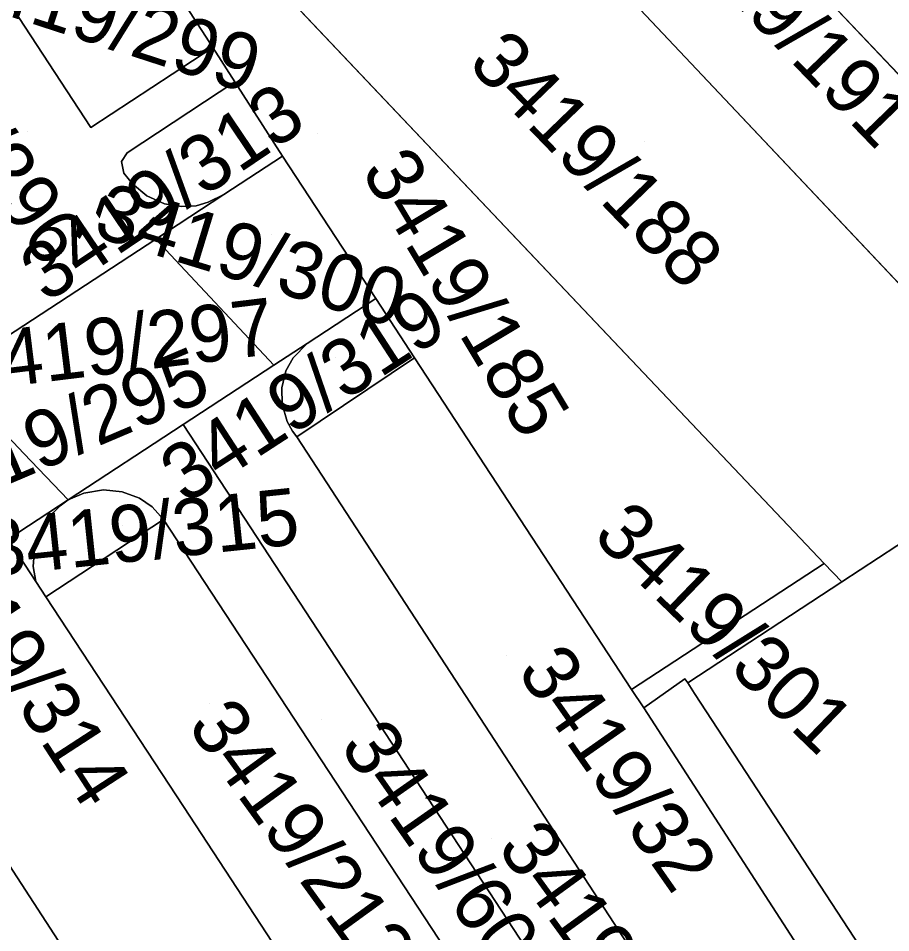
# Model space of a CAD drawing. Extents: x -262715 to -259381, y -1237238 to -1231182.
# Drawn here: x -261973.76 to -261943.03, y -1235771.55 to -1235739.35 of the extents above; entities that cross this region are included whole.
import ezdxf

# ---------------------------------------------------------------- set-up
doc = ezdxf.new("R2010")
doc.units = 0
for name, color, linetype in [('body_kn', 7, 'Continuous'), ('kladpar_druhypozemkov', 7, 'Continuous'), ('kladpar_hranice', 7, 'Continuous'), ('kladpar_parcelnecisla', 7, 'Continuous'), ('kladpar_plochy', 7, 'Continuous'), ('kladpar_sipky', 7, 'Continuous')]:
    doc.layers.add(name, color=color, linetype=linetype)

msp = doc.modelspace()

# ---------------------------------------------------------------- linework, layer by layer
at = {"layer": 'body_kn'}
for p, q in [((-261966.91, -1235740.38), (-261966.91, -1235740.38)), ((-261966.91, -1235740.38), (-261966.91, -1235740.38)), ((-261966.13, -1235741.59), (-261966.13, -1235741.59)), ((-261971.21, -1235743.19), (-261971.21, -1235743.19)), ((-261969.92, -1235744.09), (-261969.92, -1235744.09)), ((-261964.45, -1235744.2), (-261964.45, -1235744.2)), ((-261964.45, -1235744.2), (-261964.45, -1235744.2)), ((-261970.12, -1235744.39), (-261970.12, -1235744.39)), ((-261970.04, -1235744.81), (-261970.04, -1235744.81)), ((-261969.74, -1235745.18), (-261969.74, -1235745.18)), ((-261966.52, -1235745.55), (-261966.52, -1235745.55)), ((-261969.23, -1235745.6), (-261969.23, -1235745.6)), ((-261967.07, -1235745.83), (-261967.07, -1235745.83)), ((-261968.61, -1235745.89), (-261968.61, -1235745.89)), ((-261968.01, -1235745.98), (-261968.01, -1235745.98)), ((-261967.5, -1235745.96), (-261967.5, -1235745.96)), ((-261968.92, -1235747.13), (-261968.92, -1235747.13)), ((-261968.92, -1235747.13), (-261968.92, -1235747.13)), ((-261961.17, -1235749.22), (-261961.17, -1235749.22)), ((-261963.58, -1235750.8), (-261963.58, -1235750.8)), ((-261964.08, -1235751.31), (-261964.08, -1235751.31)), ((-261959.8, -1235751.31), (-261959.8, -1235751.31)), ((-261959.8, -1235751.31), (-261959.8, -1235751.31)), ((-261964.76, -1235751.57), (-261964.76, -1235751.57)), ((-261964.76, -1235751.57), (-261964.76, -1235751.57)), ((-261964.33, -1235751.77), (-261964.33, -1235751.77)), ((-261964.48, -1235752.37), (-261964.48, -1235752.37)), ((-261964.47, -1235752.94), (-261964.47, -1235752.94)), ((-261964.29, -1235753.55), (-261964.29, -1235753.55)), ((-261967.95, -1235753.66), (-261967.95, -1235753.66)), ((-261967.95, -1235753.66), (-261967.95, -1235753.66)), ((-261964.1, -1235753.89), (-261964.1, -1235753.89)), ((-261963.95, -1235754.09), (-261963.95, -1235754.09)), ((-261963.95, -1235754.09), (-261963.95, -1235754.09)), ((-261973.56, -1235754.68), (-261973.56, -1235754.68)), ((-261971.45, -1235756.07), (-261971.45, -1235756.07)), ((-261970.76, -1235755.96), (-261970.76, -1235755.96)), ((-261970.1, -1235756.03), (-261970.1, -1235756.03)), ((-261972, -1235756.31), (-261972, -1235756.31)), ((-261972, -1235756.31), (-261972, -1235756.31)), ((-261969.49, -1235756.25), (-261969.49, -1235756.25)), ((-261972.29, -1235756.52), (-261972.29, -1235756.52)), ((-261969.05, -1235756.56), (-261969.05, -1235756.56)), ((-261972.72, -1235756.94), (-261972.72, -1235756.94)), ((-261968.64, -1235757), (-261968.64, -1235757)), ((-261968.64, -1235757), (-261968.64, -1235757)), ((-261973.06, -1235757.55), (-261973.06, -1235757.55)), ((-261973.19, -1235758.06), (-261973.19, -1235758.06)), ((-261973.24, -1235758.66), (-261973.24, -1235758.66)), ((-261945.37, -1235758.55), (-261945.37, -1235758.55)), ((-261945.37, -1235758.55), (-261945.37, -1235758.55)), ((-261973.14, -1235759.18), (-261973.14, -1235759.18)), ((-261944.75, -1235759.2), (-261944.75, -1235759.2)), ((-261944.75, -1235759.2), (-261944.75, -1235759.2)), ((-261972.79, -1235759.72), (-261972.79, -1235759.72)), ((-261972.79, -1235759.72), (-261972.79, -1235759.72)), ((-261950.28, -1235762.61), (-261950.28, -1235762.61)), ((-261950.18, -1235762.76), (-261950.18, -1235762.76)), ((-261950.18, -1235762.76), (-261950.18, -1235762.76)), ((-261952.16, -1235762.99), (-261952.16, -1235762.99)), ((-261949.94, -1235763.13), (-261949.94, -1235763.13)), ((-261951.72, -1235763.63), (-261951.72, -1235763.63)), ((-261951.72, -1235763.63), (-261951.72, -1235763.63)), ((-261967.94, -1235767.11), (-261967.94, -1235767.11)), ((-261973.07, -1235770.72), (-261973.07, -1235770.72))]:
    msp.add_line(p, q, dxfattribs=at)
at = {"layer": 'kladpar_druhypozemkov'}
for p, q in [((-261973.42, -1235743.34), (-261973.42, -1235743.34)), ((-261963.23, -1235743.41), (-261963.23, -1235743.41)), ((-261967.62, -1235743.88), (-261967.62, -1235743.88)), ((-261951.7, -1235743.7), (-261951.7, -1235743.7)), ((-261964.83, -1235746.95), (-261964.83, -1235746.95)), ((-261970.19, -1235750.28), (-261970.19, -1235750.28)), ((-261962.57, -1235751.28), (-261962.57, -1235751.28)), ((-261970.09, -1235757.23), (-261970.09, -1235757.23)), ((-261973.49, -1235757.71), (-261973.49, -1235757.71)), ((-261947.28, -1235760.58), (-261947.28, -1235760.58)), ((-261956.55, -1235761.78), (-261956.55, -1235761.78)), ((-261967.01, -1235763.47), (-261967.01, -1235763.47)), ((-261963.07, -1235764.03), (-261963.07, -1235764.03)), ((-261957.08, -1235768.25), (-261957.08, -1235768.25))]:
    msp.add_line(p, q, dxfattribs=at)
at = {"layer": 'kladpar_hranice'}
for p, q in [((-261933.69, -1235750.9), (-261955.68, -1235727.67)), ((-261955.68, -1235727.67), (-261933.69, -1235750.9)), ((-261938, -1235753.72), (-261959.95, -1235730.45)), ((-261967.39, -1235735.31), (-261945.37, -1235758.55)), ((-261964.76, -1235751.57), (-261968.92, -1235747.13)), ((-261968.92, -1235747.13), (-261964.76, -1235751.57)), ((-261972, -1235756.31), (-261974.12, -1235757.69)), ((-261945.37, -1235758.55), (-261944.75, -1235759.2)), ((-261944.75, -1235759.2), (-261950.18, -1235762.76))]:
    msp.add_line(p, q, dxfattribs=at)
for points in [[(-262003.07, -1235715.88), (-261995.02, -1235727.16), (-261984.24, -1235742.27), (-261982.65, -1235744.7), (-261981.81, -1235745.97), (-261978.73, -1235750.67), (-261978.42, -1235751.14), (-261977.41, -1235752.68), (-261974.12, -1235757.69), (-261973.14, -1235759.18), (-261972.79, -1235759.72), (-261967.94, -1235767.11), (-261964.38, -1235772.54), (-261961.64, -1235776.72), (-261949.4, -1235795.38), (-261942.77, -1235806.52), (-261928.71, -1235830.14), (-261924.58, -1235837.08), (-261915.18, -1235853.36)], [(-261931.33, -1235851.2), (-261935.73, -1235843.8), (-261960.13, -1235804.5), (-261979.55, -1235774.83), (-261996.35, -1235748.74), (-262013.51, -1235721.8), (-262007.21, -1235718.92), (-262002.02, -1235726.66), (-261988.64, -1235746.76), (-261973.07, -1235770.72), (-261954.28, -1235799.67), (-261929.13, -1235840.69), (-261916.72, -1235862.21), (-261911.45, -1235872.23)], [(-261911.45, -1235872.23), (-261916.72, -1235862.21), (-261929.13, -1235840.69), (-261954.28, -1235799.67), (-261973.07, -1235770.72), (-261988.64, -1235746.76), (-262002.02, -1235726.66), (-262007.21, -1235718.92)], [(-261959.95, -1235730.45), (-261938, -1235753.72), (-261937.38, -1235754.37)], [(-261945.37, -1235758.55), (-261952.16, -1235762.99), (-261959.8, -1235751.31), (-261961.17, -1235749.22), (-261964.45, -1235744.2), (-261966.13, -1235741.59), (-261966.91, -1235740.38), (-261969.84, -1235735.84), (-261970.23, -1235735.23), (-261970.52, -1235734.74), (-261970.16, -1235734.55), (-261969.03, -1235736.38), (-261967.39, -1235735.31)], [(-261975.6, -1235738.81), (-261970.23, -1235735.23), (-261969.84, -1235735.84), (-261974.16, -1235738.67), (-261971.21, -1235743.19), (-261966.91, -1235740.38), (-261966.13, -1235741.59), (-261969.92, -1235744.09), (-261970.12, -1235744.39), (-261970.04, -1235744.81), (-261969.74, -1235745.18), (-261969.23, -1235745.6), (-261968.61, -1235745.89), (-261968.01, -1235745.98), (-261967.5, -1235745.96), (-261967.07, -1235745.83), (-261966.52, -1235745.55), (-261968.92, -1235747.13), (-261975.44, -1235751.39)], [(-261944.75, -1235759.2), (-261945.37, -1235758.55), (-261967.39, -1235735.31)], [(-261966.91, -1235740.38), (-261971.21, -1235743.19), (-261974.16, -1235738.67), (-261969.84, -1235735.84), (-261966.91, -1235740.38)], [(-261941.49, -1235776.06), (-261949.94, -1235763.13), (-261950.18, -1235762.76), (-261944.75, -1235759.2), (-261940.87, -1235756.66), (-261942.45, -1235754.27), (-261940.52, -1235752.99), (-261938.94, -1235755.39), (-261937.38, -1235754.37), (-261933.08, -1235751.55), (-261929.13, -1235748.97), (-261922.69, -1235744.74), (-261919.47, -1235742.63), (-261916.3, -1235740.55), (-261916, -1235741.01), (-261910.41, -1235749.59), (-261905.01, -1235757.89), (-261902.93, -1235761.09)], [(-261964.45, -1235744.2), (-261966.52, -1235745.55), (-261967.07, -1235745.83), (-261967.5, -1235745.96), (-261968.01, -1235745.98), (-261968.61, -1235745.89), (-261969.23, -1235745.6), (-261969.74, -1235745.18), (-261970.04, -1235744.81), (-261970.12, -1235744.39), (-261969.92, -1235744.09), (-261966.13, -1235741.59), (-261964.45, -1235744.2)], [(-261968.92, -1235747.13), (-261966.52, -1235745.55), (-261964.45, -1235744.2), (-261961.17, -1235749.22), (-261963.58, -1235750.8), (-261964.76, -1235751.57)], [(-261976.2, -1235751.89), (-261975.44, -1235751.39), (-261968.92, -1235747.13)], [(-261959.8, -1235751.31), (-261963.95, -1235754.09), (-261964.1, -1235753.89), (-261964.29, -1235753.55), (-261964.47, -1235752.94), (-261964.48, -1235752.37), (-261964.33, -1235751.77), (-261964.08, -1235751.31), (-261963.58, -1235750.8), (-261961.17, -1235749.22), (-261959.8, -1235751.31)], [(-261967.95, -1235753.66), (-261964.76, -1235751.57), (-261963.58, -1235750.8), (-261964.08, -1235751.31), (-261964.33, -1235751.77), (-261964.48, -1235752.37), (-261964.47, -1235752.94), (-261964.29, -1235753.55), (-261964.1, -1235753.89), (-261963.95, -1235754.09), (-261946.67, -1235780.57)], [(-261963.95, -1235754.09), (-261959.8, -1235751.31), (-261952.16, -1235762.99), (-261951.72, -1235763.63), (-261942.53, -1235777.85), (-261946.67, -1235780.57), (-261963.95, -1235754.09)], [(-261964.76, -1235751.57), (-261967.95, -1235753.66), (-261972, -1235756.31)], [(-261972, -1235756.31), (-261973.56, -1235754.68), (-261976.2, -1235751.89)], [(-261976.2, -1235751.89), (-261973.56, -1235754.68), (-261972, -1235756.31)], [(-261937.38, -1235754.37), (-261938.94, -1235755.39), (-261940.52, -1235752.99), (-261942.45, -1235754.27), (-261940.87, -1235756.66), (-261944.75, -1235759.2)], [(-261972, -1235756.31), (-261967.95, -1235753.66), (-261945.97, -1235787.22), (-261946.38, -1235792.77)], [(-261946.38, -1235792.77), (-261945.97, -1235787.22), (-261967.95, -1235753.66)], [(-261968.64, -1235757), (-261972.79, -1235759.72), (-261973.14, -1235759.18), (-261973.24, -1235758.66), (-261973.19, -1235758.06), (-261973.06, -1235757.55), (-261972.72, -1235756.94), (-261972.29, -1235756.52), (-261972, -1235756.31), (-261971.45, -1235756.07), (-261970.76, -1235755.96), (-261970.1, -1235756.03), (-261969.49, -1235756.25), (-261969.05, -1235756.56), (-261968.64, -1235757)], [(-261951, -1235787.91), (-261950.81, -1235787.69), (-261950.56, -1235787.38), (-261950.29, -1235786.93), (-261950.15, -1235786.47), (-261950.12, -1235786.02), (-261950.17, -1235785.56), (-261950.35, -1235785.02), (-261950.58, -1235784.59), (-261957.27, -1235774.34), (-261968.64, -1235757), (-261969.05, -1235756.56), (-261969.49, -1235756.25), (-261970.1, -1235756.03), (-261970.76, -1235755.96), (-261971.45, -1235756.07), (-261972, -1235756.31)], [(-261972, -1235756.31), (-261972.29, -1235756.52), (-261972.72, -1235756.94), (-261973.06, -1235757.55), (-261973.19, -1235758.06), (-261973.24, -1235758.66), (-261973.14, -1235759.18), (-261974.12, -1235757.69), (-261972, -1235756.31)], [(-261972.79, -1235759.72), (-261968.64, -1235757), (-261957.27, -1235774.34), (-261959.54, -1235775.81), (-261961.35, -1235777.03)], [(-261950.18, -1235762.76), (-261950.28, -1235762.61), (-261951.72, -1235763.63), (-261952.16, -1235762.99), (-261945.37, -1235758.55)], [(-261961.64, -1235776.72), (-261964.38, -1235772.54), (-261967.94, -1235767.11), (-261972.79, -1235759.72)], [(-261951.72, -1235763.63), (-261950.28, -1235762.61), (-261950.18, -1235762.76), (-261949.94, -1235763.13), (-261941.49, -1235776.06), (-261936.77, -1235783.27), (-261941.58, -1235786.56), (-261941.84, -1235786.72), (-261942.15, -1235786.76), (-261942.48, -1235786.71), (-261942.8, -1235786.46), (-261946.67, -1235780.57), (-261942.53, -1235777.85), (-261951.72, -1235763.63)]]:
    msp.add_lwpolyline(points, dxfattribs=at)
at = {"layer": 'kladpar_plochy'}
for points in [[(-261916.72, -1235862.21), (-261929.13, -1235840.69), (-261954.28, -1235799.67), (-261973.07, -1235770.72), (-261988.64, -1235746.76), (-262002.02, -1235726.66), (-262007.21, -1235718.92), (-262019.79, -1235696.69)], [(-262003.07, -1235715.88), (-261995.02, -1235727.16), (-261984.24, -1235742.27), (-261982.65, -1235744.7), (-261981.81, -1235745.97), (-261978.73, -1235750.67), (-261978.42, -1235751.14), (-261977.41, -1235752.68), (-261974.12, -1235757.69), (-261973.14, -1235759.18), (-261972.79, -1235759.72), (-261967.94, -1235767.11), (-261964.38, -1235772.54), (-261961.64, -1235776.72), (-261949.4, -1235795.38), (-261942.77, -1235806.52), (-261928.71, -1235830.14), (-261924.58, -1235837.08), (-261915.18, -1235853.36)], [(-261975.6, -1235738.81), (-261970.23, -1235735.23), (-261969.84, -1235735.84), (-261974.16, -1235738.67), (-261971.21, -1235743.19), (-261966.91, -1235740.38), (-261966.13, -1235741.59), (-261969.92, -1235744.09), (-261970.12, -1235744.39), (-261970.04, -1235744.81), (-261969.74, -1235745.18), (-261969.23, -1235745.6), (-261968.61, -1235745.89), (-261968.01, -1235745.98), (-261967.5, -1235745.96), (-261967.07, -1235745.83), (-261966.52, -1235745.55), (-261968.92, -1235747.13), (-261975.44, -1235751.39)], [(-261941.49, -1235776.06), (-261949.94, -1235763.13), (-261950.18, -1235762.76), (-261944.75, -1235759.2), (-261940.87, -1235756.66), (-261942.45, -1235754.27), (-261940.52, -1235752.99), (-261938.94, -1235755.39), (-261937.38, -1235754.37), (-261933.08, -1235751.55), (-261929.13, -1235748.97), (-261922.69, -1235744.74), (-261919.47, -1235742.63), (-261916.3, -1235740.55), (-261916, -1235741.01), (-261910.41, -1235749.59), (-261905.01, -1235757.89), (-261902.93, -1235761.09), (-261905.58, -1235762.82), (-261912.05, -1235767.06), (-261915.99, -1235769.64), (-261920.27, -1235772.45)], [(-261945.97, -1235787.22), (-261967.95, -1235753.66), (-261964.76, -1235751.57), (-261963.58, -1235750.8), (-261964.08, -1235751.31), (-261964.33, -1235751.77), (-261964.48, -1235752.37), (-261964.47, -1235752.94), (-261964.29, -1235753.55), (-261964.1, -1235753.89), (-261963.95, -1235754.09), (-261946.67, -1235780.57)]]:
    msp.add_lwpolyline(points, dxfattribs=at)
for points in [[(-261931.33, -1235851.2), (-261935.73, -1235843.8), (-261960.13, -1235804.5), (-261979.55, -1235774.83), (-261996.35, -1235748.74), (-262013.51, -1235721.8), (-262007.21, -1235718.92), (-262002.02, -1235726.66), (-261988.64, -1235746.76), (-261973.07, -1235770.72), (-261954.28, -1235799.67), (-261929.13, -1235840.69), (-261916.72, -1235862.21), (-261911.45, -1235872.23)], [(-261953.19, -1235723.48), (-261929.74, -1235748.32), (-261933.69, -1235750.9), (-261955.68, -1235727.67), (-261953.31, -1235726.12), (-261954.49, -1235724.32)], [(-261955.68, -1235727.67), (-261933.69, -1235750.9), (-261938, -1235753.72), (-261959.95, -1235730.45)], [(-261959.95, -1235730.45), (-261938, -1235753.72), (-261937.38, -1235754.37), (-261938.94, -1235755.39), (-261940.52, -1235752.99), (-261942.45, -1235754.27), (-261940.87, -1235756.66), (-261944.75, -1235759.2), (-261945.37, -1235758.55), (-261967.39, -1235735.31)], [(-261945.37, -1235758.55), (-261952.16, -1235762.99), (-261959.8, -1235751.31), (-261961.17, -1235749.22), (-261964.45, -1235744.2), (-261966.13, -1235741.59), (-261966.91, -1235740.38), (-261969.84, -1235735.84), (-261970.23, -1235735.23), (-261970.52, -1235734.74), (-261970.16, -1235734.55), (-261969.03, -1235736.38), (-261967.39, -1235735.31)], [(-261966.91, -1235740.38), (-261971.21, -1235743.19), (-261974.16, -1235738.67), (-261969.84, -1235735.84)], [(-261964.45, -1235744.2), (-261966.52, -1235745.55), (-261967.07, -1235745.83), (-261967.5, -1235745.96), (-261968.01, -1235745.98), (-261968.61, -1235745.89), (-261969.23, -1235745.6), (-261969.74, -1235745.18), (-261970.04, -1235744.81), (-261970.12, -1235744.39), (-261969.92, -1235744.09), (-261966.13, -1235741.59)], [(-261964.76, -1235751.57), (-261968.92, -1235747.13), (-261966.52, -1235745.55), (-261964.45, -1235744.2), (-261961.17, -1235749.22), (-261963.58, -1235750.8)], [(-261972, -1235756.31), (-261973.56, -1235754.68), (-261976.2, -1235751.89), (-261975.44, -1235751.39), (-261968.92, -1235747.13), (-261964.76, -1235751.57), (-261967.95, -1235753.66)], [(-261959.8, -1235751.31), (-261963.95, -1235754.09), (-261964.1, -1235753.89), (-261964.29, -1235753.55), (-261964.47, -1235752.94), (-261964.48, -1235752.37), (-261964.33, -1235751.77), (-261964.08, -1235751.31), (-261963.58, -1235750.8), (-261961.17, -1235749.22)], [(-261963.95, -1235754.09), (-261959.8, -1235751.31), (-261952.16, -1235762.99), (-261951.72, -1235763.63), (-261942.53, -1235777.85), (-261946.67, -1235780.57)], [(-261974.12, -1235757.69), (-261977.41, -1235752.68), (-261976.2, -1235751.89), (-261973.56, -1235754.68), (-261972, -1235756.31)], [(-261972, -1235756.31), (-261967.95, -1235753.66), (-261945.97, -1235787.22), (-261946.38, -1235792.77), (-261951, -1235787.91), (-261950.81, -1235787.69), (-261950.56, -1235787.38), (-261950.29, -1235786.93), (-261950.15, -1235786.47), (-261950.12, -1235786.02), (-261950.17, -1235785.56), (-261950.35, -1235785.02), (-261950.58, -1235784.59), (-261957.27, -1235774.34), (-261968.64, -1235757), (-261969.05, -1235756.56), (-261969.49, -1235756.25), (-261970.1, -1235756.03), (-261970.76, -1235755.96), (-261971.45, -1235756.07)], [(-261968.64, -1235757), (-261972.79, -1235759.72), (-261973.14, -1235759.18), (-261973.24, -1235758.66), (-261973.19, -1235758.06), (-261973.06, -1235757.55), (-261972.72, -1235756.94), (-261972.29, -1235756.52), (-261972, -1235756.31), (-261971.45, -1235756.07), (-261970.76, -1235755.96), (-261970.1, -1235756.03), (-261969.49, -1235756.25), (-261969.05, -1235756.56)], [(-261972, -1235756.31), (-261972.29, -1235756.52), (-261972.72, -1235756.94), (-261973.06, -1235757.55), (-261973.19, -1235758.06), (-261973.24, -1235758.66), (-261973.14, -1235759.18), (-261974.12, -1235757.69)], [(-261972.79, -1235759.72), (-261968.64, -1235757), (-261957.27, -1235774.34), (-261959.54, -1235775.81), (-261961.35, -1235777.03), (-261961.64, -1235776.72), (-261964.38, -1235772.54), (-261967.94, -1235767.11)], [(-261950.18, -1235762.76), (-261950.28, -1235762.61), (-261951.72, -1235763.63), (-261952.16, -1235762.99), (-261945.37, -1235758.55), (-261944.75, -1235759.2)], [(-261951.72, -1235763.63), (-261950.28, -1235762.61), (-261950.18, -1235762.76), (-261949.94, -1235763.13), (-261941.49, -1235776.06), (-261936.77, -1235783.27), (-261941.58, -1235786.56), (-261941.84, -1235786.72), (-261942.15, -1235786.76), (-261942.48, -1235786.71), (-261942.8, -1235786.46), (-261946.67, -1235780.57), (-261942.53, -1235777.85)]]:
    msp.add_lwpolyline(points, close=True, dxfattribs=at)
at = {"layer": 'kladpar_sipky'}
msp.add_line((-261973.57, -1235758.19), (-261973.57, -1235758.19), dxfattribs=at)

# ---------------------------------------------------------------- texts
at = {"layer": 'kladpar_parcelnecisla'}
for s, rotation, p in [('3419/194', 314, (-261947.327, -1235733.565)), ('3419/191', 314, (-261951.253, -1235736.019)), ('3419/299', 342, (-261976.264, -1235738.569)), ('3419/296', 306, (-261979.373, -1235739.19)), ('3419/188', 314, (-261957.966, -1235740.985)), ('3419/313', 34, (-261972.772, -1235749.402)), ('3419/185', 301, (-261961.706, -1235744.728)), ('3419/300', 343, (-261971.176, -1235747.006)), ('3419/319', 33, (-261967.878, -1235756.489)), ('3419/297', 7, (-261975.736, -1235752.519)), ('3419/295', 23, (-261977.134, -1235757.055)), ('3419/315', 6, (-261974.886, -1235759.023)), ('3419/301', 316, (-261953.571, -1235757.638)), ('3419/314', 303, (-261977.469, -1235757.942)), ('3419/32', 305, (-261956.218, -1235762.353)), ('3419/212', 306, (-261967.834, -1235764.281)), ('3419/60', 305, (-261962.468, -1235764.992)), ('3419/209', 306, (-261956.922, -1235768.565))]:
    msp.add_text(s, height=2, rotation=rotation, dxfattribs=at).set_placement(p)

doc.saveas('drawing.dxf')
